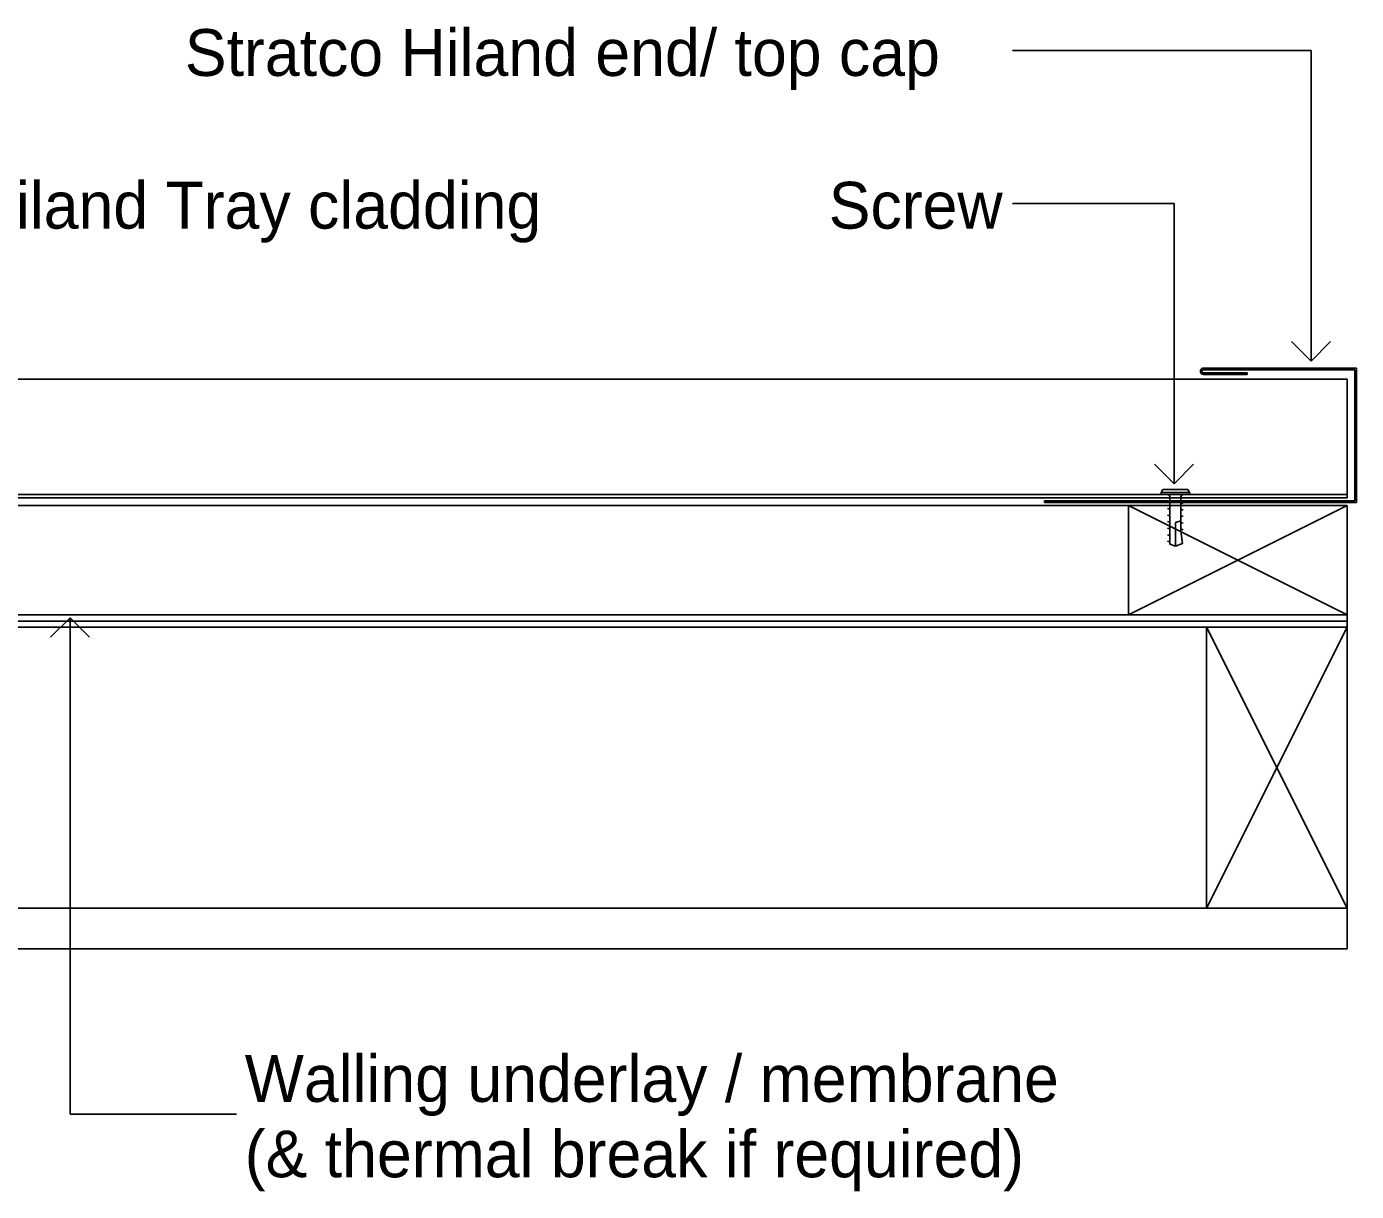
# Model space of a CAD drawing. Extents: x -2.36 to 6.66, y -3.72 to 4.13.
# Drawn here: x 4.3584 to 4.7845, y -3.7197 to -3.3466 of the extents above; entities that cross this region are included whole.
import ezdxf

# ---------------------------------------------------------------- set-up
doc = ezdxf.new("R2010")
doc.units = 0
for name, color, linetype in [('A-____-____-IDEN', 7, 'Continuous'), ('A-DETL-____-MEDM', 7, 'Continuous'), ('A-DETL-GENF-OTLN', 7, 'Continuous'), ('A-WALL-____-MCUT', 7, 'Continuous'), ('A-WALL-____-PATT', 7, 'Continuous'), ('A-WALL-FNSH-MCUT', 7, 'Continuous')]:
    doc.layers.add(name, color=color, linetype=linetype)

# ---------------------------------------------------------------- blocks, each defined once
blk = doc.blocks.new('Detail_Stratco_Cladding Side Profile - 38mm-Detail Flashings - Hiland Nailstrip End Caps')
at = {"layer": 'A-DETL-____-MEDM'}
for p, q in [((0.7878074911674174, 0.000999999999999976), (0, 0.000999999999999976)), ((0, 0), (0.7878074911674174, 0)), ((0.7878074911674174, 0), (0.7878074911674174, 0.000999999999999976))]:
    blk.add_line(p, q, dxfattribs=at)
at = {"layer": 'A-DETL-GENF-OTLN'}
for p, q in [((0, 0.038000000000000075), (0.7878074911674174, 0.038000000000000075)), ((0.7878074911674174, 0.038000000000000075), (0.7878074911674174, 0))]:
    blk.add_line(p, q, dxfattribs=at)
blk = doc.blocks.new('DET_ST_Framing Detail Timber - 35x70 Batten-V17-Detail Flashings - Hiland Nailstrip End Caps')
at = {"layer": 'A-DETL-____-MEDM'}
for p, q in [((0.06999999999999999, 0), (0, 0)), ((0, 0), (0, -0.034999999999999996)), ((0.06999999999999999, -0.034999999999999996), (0.06999999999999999, 0)), ((0, -0.034999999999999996), (0.06999999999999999, -0.034999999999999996))]:
    blk.add_line(p, q, dxfattribs=at)
at = {"layer": 'A-DETL-GENF-OTLN'}
for p, q in [((0, -0.035000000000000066), (0.06999999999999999, 4.229949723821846e-18)), ((0.06999999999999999, -0.035000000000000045), (0, 0))]:
    blk.add_line(p, q, dxfattribs=at)
blk = doc.blocks.new('DET_ST_Framing Detail Timber - 45x90-V18-Detail Flashings - Hiland Nailstrip End Caps')
at = {"layer": 'A-DETL-____-MEDM'}
for p, q in [((0.09000000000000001, 0), (0, 0)), ((0, 0), (0, -0.045000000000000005)), ((0.09000000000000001, -0.045000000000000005), (0.09000000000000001, 0)), ((0, -0.045000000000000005), (0.09000000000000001, -0.045000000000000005))]:
    blk.add_line(p, q, dxfattribs=at)
at = {"layer": 'A-DETL-GENF-OTLN'}
for p, q in [((0, -0.04500000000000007), (0.09000000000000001, 0)), ((0.09000000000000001, -0.045000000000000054), (0, 0))]:
    blk.add_line(p, q, dxfattribs=at)
blk = doc.blocks.new('Detail_Stratco_Hiland_Tray_End Top - Rib Height 38mm-Detail Flashings - Hiland Nailstrip End Caps')
at = {"layer": 'A-DETL-GENF-OTLN'}
for p, q in [((-0.11208857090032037, 0.13087846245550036), (-0.11208857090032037, 0.08787846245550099)), ((-0.11208857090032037, 0.13087846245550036), (-0.012088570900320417, 0.13087846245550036)), ((-0.11158857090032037, 0.13037846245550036), (-0.11158857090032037, 0.08837846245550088)), ((-0.11158857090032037, 0.13037846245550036), (-0.012088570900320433, 0.13037846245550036)), ((-0.012088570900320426, 0.13087846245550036), (-0.012088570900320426, 0.13037846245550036)), ((-0.07708857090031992, 0.08987846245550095), (-0.06308857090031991, 0.08987846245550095)), ((-0.07708857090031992, 0.08987846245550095), (-0.07708857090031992, 0.08937846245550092)), ((-0.11208857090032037, 0.08787846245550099), (-0.06308857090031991, 0.08787846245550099)), ((-0.11158857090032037, 0.08837846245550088), (-0.06308857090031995, 0.08837846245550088)), ((-0.07708857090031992, 0.08937846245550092), (-0.06308857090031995, 0.08937846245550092))]:
    blk.add_line(p, q, dxfattribs=at)
for centre, radius in [((-0.06308857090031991, 0.08887846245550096), 0.0010000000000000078), ((-0.06308857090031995, 0.08887846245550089), 0.0005000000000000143)]:
    blk.add_arc(centre, radius, 269.99999999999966, 90, dxfattribs=at)
blk = doc.blocks.new('DET_Screw Metal Wafer - DET_Screw Metal Wafer-Detail Flashings - Hiland Nailstrip End Caps')
at = {"layer": 'A-DETL-GENF-OTLN'}
for p, q in [((-0.004552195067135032, 0.0007104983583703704), (-0.004005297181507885, 0.0016406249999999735)), ((0.004552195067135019, 0.0007104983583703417), (-0.00455219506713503, 0.0007104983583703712)), ((-0.004005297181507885, 0.001640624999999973), (0.004005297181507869, 0.0016406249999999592)), ((0.004005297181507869, 0.0016406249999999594), (0.004557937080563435, 0.0007007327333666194)), ((-0.004099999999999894, -3.3839597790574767e-17), (0.004099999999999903, -4.840572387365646e-17)), ((-0.001749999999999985, -0.002586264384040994), (-0.0024999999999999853, -0.002348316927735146)), ((-0.0017500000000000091, -0.015876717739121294), (-0.0017499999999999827, -0.0007999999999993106)), ((0.0017499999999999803, -0.011598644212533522), (0.0017499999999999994, -0.0007999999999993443)), ((0.0024999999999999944, -0.0028602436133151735), (0.0017499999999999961, -0.0026222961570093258)), ((-0.0017499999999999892, -0.004684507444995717), (-0.0025000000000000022, -0.004446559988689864)), ((-0.0017499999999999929, -0.006782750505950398), (-0.0025000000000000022, -0.006544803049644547)), ((4.089304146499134e-15, -0.00889755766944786), (0.001749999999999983, -0.008395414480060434)), ((0.0024999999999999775, -0.004958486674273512), (0.0017499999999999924, -0.004720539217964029)), ((0.0024999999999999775, -0.007056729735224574), (0.0017499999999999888, -0.006818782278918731)), ((-0.0017499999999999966, -0.008880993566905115), (-0.0025000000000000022, -0.008643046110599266)), ((-0.001750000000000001, -0.01097923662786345), (-0.0025000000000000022, -0.010741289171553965)), ((4.075497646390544e-15, -0.016513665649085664), (4.089026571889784e-15, -0.00889755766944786)), ((0.0024999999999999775, -0.009154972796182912), (0.0017499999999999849, -0.008917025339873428)), ((0.0024999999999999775, -0.011253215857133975), (0.0017499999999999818, -0.011015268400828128)), ((0.0017499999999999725, -0.011598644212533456), (0.002321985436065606, -0.01566853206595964)), ((-0.0017500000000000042, -0.013077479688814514), (-0.0025000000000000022, -0.012839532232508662)), ((-0.001750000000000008, -0.015175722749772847), (-0.0025000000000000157, -0.014937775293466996)), ((-0.0017500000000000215, -0.015876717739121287), (1.5862311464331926e-18, -0.01651366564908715)), ((0.002321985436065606, -0.01566853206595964), (-1.5862311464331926e-18, -0.01651366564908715))]:
    blk.add_line(p, q, dxfattribs=at)
for centre, radius, start, end in [((-0.0040999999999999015, 0.0004999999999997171), 0.0005, 156.33017610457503, 269.9999999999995), ((-0.0025499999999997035, -0.0007999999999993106), 0.0008000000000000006, 359.9999999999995, 90), ((0.002549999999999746, -0.0007999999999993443), 0.0007999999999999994, 89.99999999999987, 179.9999999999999), ((0.0040999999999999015, 0.0004999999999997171), 0.0004999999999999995, 269.9999999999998, 23.66982389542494)]:
    blk.add_arc(centre, radius, start, end, dxfattribs=at)

msp = doc.modelspace()

# ---------------------------------------------------------------- linework, layer by layer
at = {"layer": 'A-____-____-IDEN'}
for p, q in [((4.770001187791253, -3.3542775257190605), (4.674318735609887, -3.3542775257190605)), ((4.770001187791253, -3.453719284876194), (4.770001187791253, -3.3542775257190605)), ((4.726087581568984, -3.4031988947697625), (4.674318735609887, -3.4031988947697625)), ((4.726087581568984, -3.4930099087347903), (4.726087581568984, -3.4031988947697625)), ((4.770001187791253, -3.453719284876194), (4.763751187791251, -3.4474692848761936)), ((4.770001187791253, -3.453719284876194), (4.776251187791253, -3.4474692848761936)), ((4.726087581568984, -3.4930099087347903), (4.719837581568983, -3.48675990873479)), ((4.726087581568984, -3.4930099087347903), (4.732337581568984, -3.48675990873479)), ((4.372301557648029, -3.5359388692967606), (4.366051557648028, -3.5421888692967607)), ((4.372301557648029, -3.5359388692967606), (4.378551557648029, -3.5421888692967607)), ((4.372301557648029, -3.5359388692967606), (4.372301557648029, -3.6950327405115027)), ((4.372301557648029, -3.6950327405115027), (4.425668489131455, -3.6950327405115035))]:
    msp.add_line(p, q, dxfattribs=at)
at = {"layer": 'A-WALL-____-MCUT'}
for p, q in [((4.711520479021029, -3.5000000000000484), (4.063712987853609, -3.5000000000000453)), ((4.781520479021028, -3.5370000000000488), (3.993712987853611, -3.537000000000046)), ((4.711520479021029, -3.535000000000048), (4.063712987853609, -3.535000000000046)), ((4.781520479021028, -3.5390000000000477), (4.781520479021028, -3.535000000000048)), ((4.736520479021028, -3.5390000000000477), (4.038712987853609, -3.5390000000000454)), ((4.736520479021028, -3.629000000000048), (4.038712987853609, -3.6290000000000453))]:
    msp.add_line(p, q, dxfattribs=at)
at = {"layer": 'A-WALL-____-PATT'}
for p, q in [((4.711520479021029, -3.5000000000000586), (4.063712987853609, -3.5000000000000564)), ((4.711520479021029, -3.535000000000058), (4.711520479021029, -3.5000000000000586)), ((4.7815204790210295, -3.535000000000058), (3.9937129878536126, -3.535000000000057)), ((3.9937129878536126, -3.5370000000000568), (4.711520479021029, -3.537000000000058)), ((4.7815204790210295, -3.537000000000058), (3.9937129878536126, -3.5370000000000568)), ((4.063712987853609, -3.535000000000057), (4.711520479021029, -3.535000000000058)), ((4.711520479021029, -3.537000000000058), (4.7815204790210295, -3.537000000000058)), ((4.7815204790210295, -3.537000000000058), (4.7815204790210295, -3.535000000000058)), ((4.7815204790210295, -3.539000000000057), (4.7815204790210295, -3.537000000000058)), ((3.9937129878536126, -3.539000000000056), (4.736520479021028, -3.539000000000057)), ((4.736520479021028, -3.539000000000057), (4.038712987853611, -3.539000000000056)), ((4.736520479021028, -3.539000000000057), (4.7815204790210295, -3.539000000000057)), ((4.736520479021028, -3.6290000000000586), (4.736520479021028, -3.539000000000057)), ((4.7815204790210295, -3.6290000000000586), (3.9937129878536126, -3.6290000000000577)), ((4.038712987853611, -3.6290000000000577), (4.736520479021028, -3.6290000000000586)), ((4.7815204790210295, -3.64200000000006), (4.7815204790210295, -3.6290000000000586)), ((3.9937129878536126, -3.642000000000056), (4.736520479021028, -3.64200000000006)), ((4.736520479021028, -3.64200000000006), (4.7815204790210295, -3.64200000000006))]:
    msp.add_line(p, q, dxfattribs=at)
at = {"layer": 'A-WALL-FNSH-MCUT'}
for p, q in [((4.781520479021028, -3.6420000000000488), (4.781520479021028, -3.629000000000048)), ((3.993712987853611, -3.642000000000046), (4.781520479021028, -3.6420000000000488))]:
    msp.add_line(p, q, dxfattribs=at)

# ---------------------------------------------------------------- block references
at = {"layer": 'A-DETL-GENF-OTLN'}
for name, p, rotation in [('Detail_Stratco_Hiland_Tray_End Top - Rib Height 38mm-Detail Flashings - Hiland Nailstrip End Caps', (4.672431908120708, -3.3681215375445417), 180), ('DET_ST_Framing Detail Timber - 35x70 Batten-V17-Detail Flashings - Hiland Nailstrip End Caps', (4.781520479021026, -3.5350000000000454), 180), ('DET_ST_Framing Detail Timber - 45x90-V18-Detail Flashings - Hiland Nailstrip End Caps', (4.736520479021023, -3.6290000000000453), 90.0000000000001)]:
    msp.add_blockref(name, p, dxfattribs=dict(at, rotation=rotation))
for name, p in [('Detail_Stratco_Cladding Side Profile - 38mm-Detail Flashings - Hiland Nailstrip End Caps', (3.993712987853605, -3.497500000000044)), ('DET_Screw Metal Wafer - DET_Screw Metal Wafer-Detail Flashings - Hiland Nailstrip End Caps', (4.726520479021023, -3.496500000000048))]:
    msp.add_blockref(name, p, dxfattribs=at)

# ---------------------------------------------------------------- texts
at = {"layer": 'A-____-____-IDEN'}
for s, p in [('Stratco Hiland end/ top cap', (4.409068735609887, -3.362377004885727)), ('Stratco Hiland Tray cladding', (4.271326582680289, -3.411298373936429)), ('Screw', (4.615418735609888, -3.411298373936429)), ('Walling underlay / membrane', (4.428279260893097, -3.69105721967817)), ('(& thermal break if required)', (4.428279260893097, -3.715200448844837))]:
    msp.add_text(s, height=0.014999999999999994, dxfattribs=at).set_placement(p)

doc.saveas('drawing.dxf')
